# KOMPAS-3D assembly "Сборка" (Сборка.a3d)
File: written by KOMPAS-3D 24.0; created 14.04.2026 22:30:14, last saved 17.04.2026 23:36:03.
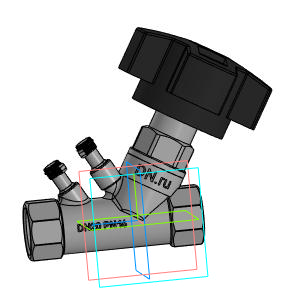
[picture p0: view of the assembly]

Document properties: Автор: tyuri; Полное имя файла: D:\Аутсорс\VB0000P-T Клапан балансировочный статический DN.ru\DN20\Исходные файлы\Сборка.a3d

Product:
- Component [detail]: Деталь1  | qty 1  | Автор: tyuri; additional columns: Типовые; source file: Деталь1 - Деталь1.m3d
- Body: Тело 1  | qty 1
    Масса: 0.426343
- Component [detail]: Ручка  | designation Деталь2  | qty 1  | Масса: 0.541971; Автор: tyuri; additional columns: Типовые; source file: Деталь2 - Деталь2.m3d
- Part/product: Сборка
    Масса: 0.968314

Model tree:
1. Эскиз:2  (labels: Ребро.Твердое тело1; Вершина.Твердое тело1; Грань.Твердое тело1)
2. Элемент вращения:1  (labels: Грань.Твердое тело1)
     Угол 1 = 360
3. Смещенная плоскость:1
     Расстояние = 40
4. Эскиз:3
5. Элемент выдавливания:1  (with: Грань.Элемент вращения:1)
     Расстояние 1 = -26.0383; Смещение 1 = 0.01
6. Эскиз:4
7. Элемент выдавливания:2  (with: Грань.Элемент вращения:1)  (labels: Грань.Твердое тело1; Твердое тело1)
     Расстояние 1 = -28.0061; Смещение 1 = 0.001; Ориентация = 2; Расстояние = -0.1

Referenced files in D:\Аутсорс\VB0000P-T Клапан балансировочный статический DN.ru\DN20\Исходные файлы\: Деталь1 - Деталь1.m3d, Деталь2 - Деталь2.m3d
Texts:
  Точка начала. Х
  Точка начала. Y
  Точка начала. Z
  DN20 PN16
  GOST 26.020 Pr3
  Деталь1 Деталь1
  Деталь2 Ручка
  Ось X.Начало координат
  Ось Z.Начало координат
